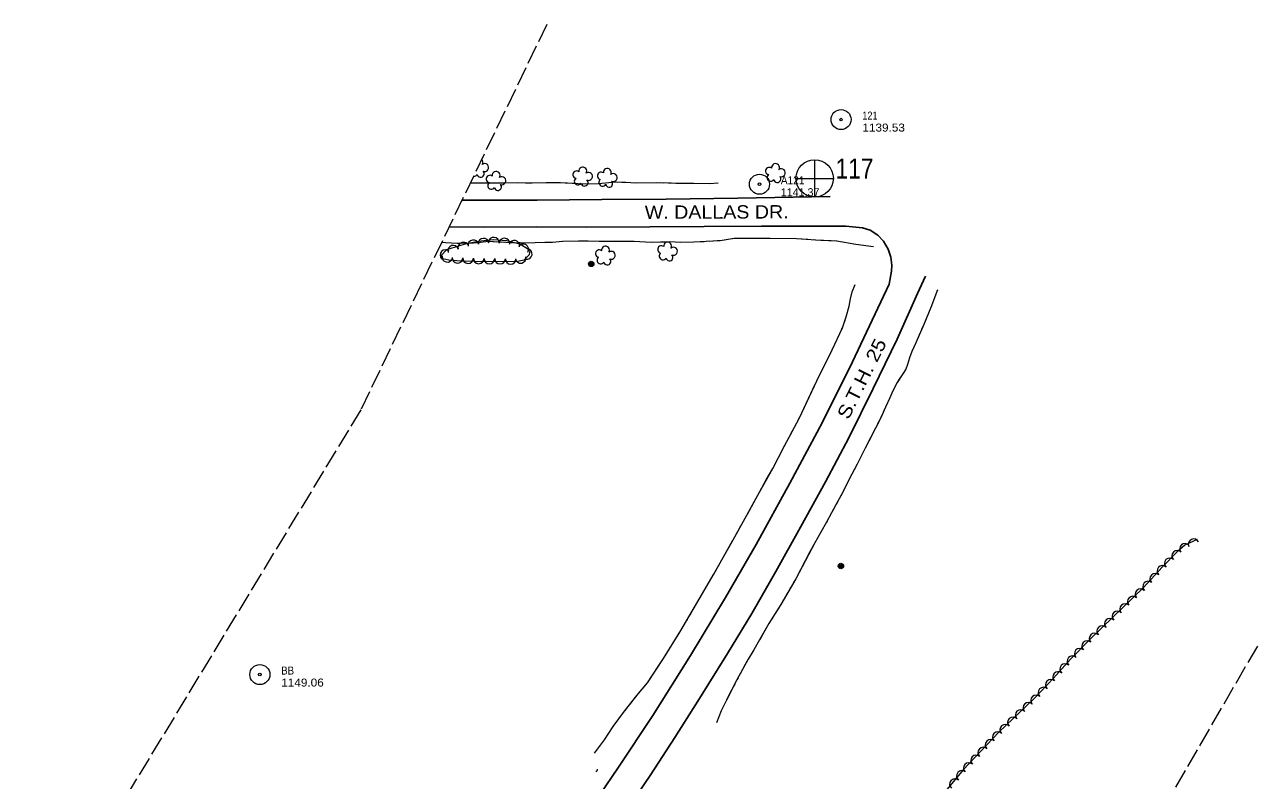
# Model space of a CAD drawing. Extents: x 301157 to 303663, y 52185 to 54539.
# Drawn here: x 302144 to 303068, y 53343 to 53910 of the extents above; entities that cross this region are included whole.
import ezdxf

# ---------------------------------------------------------------- set-up
doc = ezdxf.new("R2010")
doc.units = 0
doc.header["$LTSCALE"] = 2.4
doc.linetypes.add('LONG_DASHED', pattern=[7.5, 6, -1.5])
for name, color, linetype, lineweight in [('11', 7, 'Continuous', 25), ('14', 7, 'Continuous', 13), ('15', 7, 'Continuous', 13), ('18', 7, 'Continuous', 13), ('19', 7, 'Continuous', 13), ('4', 7, 'Continuous', 13), ('6', 7, 'Continuous', 13)]:
    doc.layers.add(name, color=color, linetype=linetype, lineweight=lineweight)

msp = doc.modelspace()

# ---------------------------------------------------------------- linework, layer by layer
at = {"layer": '11'}
for points in [[(302748.12, 53780.74), (302720.461, 53780.312), (302678.818, 53779.643), (302625.184, 53778.826), (302576.883, 53778.434), (302528.48, 53777.953), (302483.979, 53778.022), (302471.984, 53777.974)], [(302462.37, 53758.053), (302488.449, 53757.824), (302528.071, 53758.107), (302565.172, 53757.901), (302612.95, 53758.038), (302653.56, 53758.281), (302696.71, 53758.662), (302731.534, 53758.637), (302759.808, 53758.471), (302772.335, 53757.239), (302778.061, 53755.629), (302783.915, 53751.863), (302788.127, 53747.346), (302791.568, 53741.213), (302793.501, 53735.397), (302794.461, 53729.339), (302794.085, 53724.792), (302792.333, 53715.001), (302764.742, 53656.644), (302742.002, 53610.915), (302717.971, 53565.75), (302692.746, 53519.734), (302669.6, 53479.916), (302643.445, 53436.361), (302615.208, 53391.529), (302588.941, 53351.821), (302562.487, 53312.98)], [(302590.369, 53312.818), (302613.105, 53346.396), (302631.621, 53374.962), (302650.2, 53404.186), (302671.229, 53437.906), (302689.338, 53468.019), (302707.415, 53499.563), (302725.953, 53532.685), (302744.702, 53566.827), (302762.011, 53599.746), (302780.469, 53636.767), (302798.263, 53673.828), (302813.716, 53708.052), (302819.521, 53721.117)]]:
    msp.add_lwpolyline(points, dxfattribs=at)
at = {"layer": '14'}
for centre, radius in [((302568.933, 53730.187), 2.018), ((302568.922, 53730.194), 1.518), ((302568.956, 53730.173), 1.008), ((302568.951, 53730.182), 0.502), ((302756.146, 53503.564), 2.018), ((302756.135, 53503.571), 1.518), ((302756.169, 53503.55), 1.008), ((302756.164, 53503.559), 0.502)]:
    msp.add_circle(centre, radius, dxfattribs=at)
at = {"layer": '15'}
msp.add_arc((302572.452, 53350.88), 1.257, 271.47424, 17.7138, dxfattribs=at)
at = {"layer": '18'}
msp.add_lwpolyline([(302512.501, 53731.917), (302518.545, 53733.193), (302522.664, 53737.242), (302523.217, 53740.32), (302515.447, 53745.103), (302505.579, 53747.471), (302495.43, 53748.292), (302484.234, 53747.099), (302473.358, 53744.869), (302460.406, 53740.717), (302456.517, 53736.587), (302457.633, 53734.167), (302462.215, 53733.194), (302471.134, 53732.617), (302481.868, 53732.331)], close=True, dxfattribs=at)
msp.add_lwpolyline([(303023.41, 53523.48), (303014.024, 53519.115), (303008.086, 53513.917), (302997.199, 53502.874), (302982.89, 53487.313), (302960.068, 53465.27), (302943.057, 53448.804), (302928.36, 53433.726), (302915.552, 53419.544), (302901.279, 53404.516), (302874.497, 53378.955), (302847.963, 53350.654), (302828.253, 53327.174)], dxfattribs=at)
for centre, radius, start, end in [((302484.701, 53806.423), 2.974, 327.63186, 46.39781), ((302481.127, 53798.884), 2.783, 262.10554, 328.29081), ((302486.066, 53797.874), 2.611, 189.98791, 47.92051), ((302489.06, 53802.515), 2.975, 245.28267, 128.25594), ((302497.643, 53796.537), 2.974, 327.63186, 188.86574), ((302557.927, 53797.196), 2.777, 50.60275, 258.37574), ((302562.627, 53799.8), 2.974, 327.63186, 188.86574), ((302566.986, 53795.892), 2.975, 245.28267, 128.25594), ((302576.316, 53796.346), 2.777, 50.60275, 258.37574), ((302581.016, 53798.95), 2.974, 327.63186, 188.86574), ((302585.375, 53795.042), 2.975, 245.28267, 128.25594), ((302702.477, 53799.916), 2.777, 50.60275, 258.37574), ((302707.177, 53802.52), 2.974, 327.63186, 188.86574), ((302711.536, 53798.612), 2.975, 245.28267, 128.25594), ((302492.943, 53793.933), 2.777, 50.60275, 258.37574), ((302494.069, 53788.998), 2.783, 127.27976, 328.29081), ((302499.008, 53787.988), 2.611, 189.98791, 47.92051), ((302502.002, 53792.629), 2.975, 245.28267, 128.25594), ((302559.053, 53792.261), 2.783, 127.27976, 328.29081), ((302563.992, 53791.251), 2.611, 189.98791, 47.92051), ((302577.442, 53791.411), 2.783, 127.27976, 328.29081), ((302582.381, 53790.401), 2.611, 189.98791, 47.92051), ((302703.603, 53794.981), 2.783, 127.27976, 328.29081), ((302708.542, 53793.971), 2.611, 189.98791, 47.92051), ((302465.412, 53740.126), 3.996, 17.78186, 197.76654), ((302473.021, 53742.565), 3.996, 17.78186, 197.76654), ((302480.603, 53744.22), 3.996, 11.59491, 191.57959), ((302488.289, 53745.428), 3.996, 6.08992, 186.07459), ((302495.845, 53746.16), 3.996, 355.38281, 175.36749), ((302503.81, 53745.516), 3.996, 355.38281, 175.36749), ((302511.3, 53743.947), 3.996, 346.51369, 166.49836), ((302517.951, 53741.106), 3.996, 328.39234, 148.37702), ((302579.665, 53740.581), 2.974, 327.63186, 188.86574), ((302621.549, 53741.044), 2.777, 50.60275, 258.37574), ((302626.249, 53743.648), 2.974, 327.63186, 188.86574), ((302630.608, 53739.74), 2.975, 245.28267, 128.25594), ((302459.595, 53736.805), 3.996, 46.72909, 226.71377), ((302461.058, 53735.578), 3.996, 168.01884, 348.00352), ((302468.7, 53734.87), 3.996, 176.30616, 356.29084), ((302476.604, 53734.563), 3.996, 178.48142, 358.46609), ((302484.565, 53734.386), 3.996, 179.23337, 359.21804), ((302492.555, 53734.278), 3.996, 179.23337, 359.21804), ((302500.545, 53734.17), 3.996, 179.23337, 359.21804), ((302508.535, 53734.062), 3.996, 179.23337, 359.21804), ((302515.979, 53734.789), 3.996, 191.9288, 11.91348), ((302520.612, 53737.645), 3.996, 259.82244, 79.80712), ((302574.965, 53737.977), 2.777, 50.60275, 258.37574), ((302576.091, 53733.042), 2.783, 127.27976, 328.29081), ((302581.03, 53732.032), 2.611, 189.98791, 47.92051), ((302584.024, 53736.673), 2.975, 245.28267, 128.25594), ((302622.675, 53736.109), 2.783, 127.27976, 328.29081), ((302627.614, 53735.099), 2.611, 189.98791, 47.92051), ((303014.185, 53516.481), 3.989, 41.20588, 221.19056), ((303020.674, 53519.905), 3.989, 24.94865, 204.93333), ((303008.38, 53511.242), 3.989, 45.41523, 225.39991), ((302997.284, 53499.883), 3.989, 47.40781, 227.39249), ((303002.78, 53505.562), 3.989, 45.41523, 225.39991), ((302991.885, 53494.011), 3.989, 47.40781, 227.39249), ((302980.792, 53482.384), 3.989, 44.01292, 223.9976), ((302986.486, 53488.14), 3.989, 47.40781, 227.39249), ((302969.317, 53471.301), 3.989, 44.01292, 223.9976), ((302975.054, 53476.842), 3.989, 44.01292, 223.9976), ((302963.58, 53465.76), 3.989, 44.01292, 223.9976), ((302952.117, 53454.668), 3.989, 44.07498, 224.05966), ((302957.848, 53460.216), 3.989, 44.07498, 224.05966), ((302940.807, 53443.505), 3.989, 45.74078, 225.72546), ((302946.386, 53449.121), 3.989, 44.07498, 224.05966), ((302935.24, 53437.793), 3.989, 45.74078, 225.72546), ((302924.388, 53426.213), 3.989, 47.92194, 227.90662), ((302929.734, 53432.133), 3.989, 47.92194, 227.90662), ((302913.566, 53414.422), 3.989, 46.48368, 226.46836), ((302919.042, 53420.293), 3.989, 47.92194, 227.90662), ((302908.073, 53408.638), 3.989, 46.48368, 226.46836), ((302896.727, 53397.286), 3.989, 43.67137, 223.65605), ((302902.497, 53402.793), 3.989, 43.67137, 223.65605), ((302890.957, 53391.779), 3.989, 43.67137, 223.65605), ((302879.416, 53380.764), 3.989, 43.67137, 223.65605), ((302885.187, 53386.271), 3.989, 43.67137, 223.65605), ((302868.397, 53369.397), 3.989, 46.85332, 226.838), ((302873.853, 53375.216), 3.989, 46.85332, 226.838), ((302862.942, 53363.578), 3.989, 46.85332, 226.838), ((302852.03, 53351.94), 3.989, 46.85332, 226.838), ((302857.486, 53357.759), 3.989, 46.85332, 226.838), ((302846.825, 53346.052), 3.989, 49.99629, 229.98097), ((302841.697, 53339.942), 3.989, 49.99629, 229.98097)]:
    msp.add_arc(centre, radius, start, end, dxfattribs=at)
at = {"layer": '19'}
for p, q in [((302478.303, 53791.068), (302478.926, 53791.075)), ((302482.542, 53791.063), (302484.351, 53791.039)), ((302487.967, 53790.991), (302489.775, 53790.967)), ((302549.425, 53791.078), (302551.232, 53791.019)), ((302560.256, 53790.535), (302562.059, 53790.401)), ((302621.651, 53791.216), (302623.457, 53791.155)), ((302627.071, 53791.034), (302628.878, 53790.973)), ((302503.929, 53746.313), (302501.985, 53746.416)), ((302509.762, 53746.005), (302507.818, 53746.108)), ((302515.602, 53745.924), (302513.655, 53745.946)), ((302581.738, 53747.087), (302579.791, 53747.098)), ((302587.579, 53747.052), (302585.632, 53747.063)), ((302593.419, 53747.039), (302591.473, 53747.032)), ((302659.544, 53747.211), (302657.601, 53747.105)), ((302665.374, 53747.532), (302663.431, 53747.425)), ((302671.135, 53748.485), (302669.215, 53748.16)), ((302737.209, 53748.08), (302735.268, 53748.22)), ((302743.042, 53747.781), (302741.098, 53747.88)), ((302748.876, 53747.486), (302746.931, 53747.585)), ((302754.147, 53675.456), (302755.009, 53677.283)), ((302815.221, 53677.75), (302814.483, 53676.081)), ((302817.436, 53682.758), (302816.698, 53681.089)), ((302751.561, 53669.977), (302752.423, 53671.803)), ((302813.006, 53672.743), (302812.268, 53671.073)), ((302786.882, 53616.683), (302786.125, 53615.021)), ((302718.785, 53602.838), (302719.719, 53604.629)), ((302721.588, 53608.21), (302722.523, 53610.001)), ((302782.006, 53606.874), (302781.181, 53605.245)), ((302784.482, 53611.76), (302783.657, 53610.131)), ((302715.981, 53597.465), (302716.916, 53599.256)), ((302753.687, 53551.648), (302752.81, 53550.047)), ((302683.083, 53537.172), (302684.064, 53538.938)), ((302748.366, 53542.071), (302747.491, 53540.468)), ((302751.029, 53546.859), (302750.136, 53545.266)), ((302680.141, 53531.874), (302681.122, 53533.64)), ((302660.915, 53497.488), (302675.237, 53523.044)), ((302677.199, 53526.575), (302678.18, 53528.341)), ((302718.6, 53487.599), (302717.682, 53486.021)), ((302713.09, 53478.128), (302712.172, 53476.549)), ((302715.845, 53482.864), (302714.927, 53481.285)), ((302643.083, 53466.955), (302644.117, 53468.691)), ((302636.874, 53456.543), (302637.909, 53458.279)), ((302639.979, 53461.749), (302641.013, 53463.485)), ((302681.669, 53424.595), (302680.798, 53422.99)), ((302676.504, 53414.931), (302675.663, 53413.309)), ((302598.137, 53399.941), (302599.389, 53401.525)), ((302590.763, 53390.33), (302591.965, 53391.954)), ((302594.383, 53395.19), (302595.634, 53396.774))]:
    msp.add_line(p, q, dxfattribs=at)
for points in [[(302478.303, 53791.068), (302480.428, 53791.091), (302491.957, 53790.938), (302503.32, 53791.063), (302513.36, 53791.302), (302524.595, 53791.035), (302535.106, 53791.272), (302544.233, 53791.246), (302555.691, 53790.875), (302562.572, 53790.363), (302574.08, 53790.48), (302584.827, 53791.609), (302587.913, 53791.7), (302594.969, 53791.529), (302602.402, 53791.158), (302620.266, 53791.262), (302632.986, 53790.835), (302645.798, 53790.759), (302657.782, 53790.652), (302664.121, 53791.048)], [(302493.391, 53790.954), (302503.32, 53791.063), (302513.36, 53791.302), (302519.601, 53791.154)], [(302519.601, 53791.154), (302524.595, 53791.035), (302535.106, 53791.272), (302544.233, 53791.246), (302545.812, 53791.195)], [(302554.845, 53790.902), (302555.691, 53790.875), (302556.65, 53790.804)], [(302565.674, 53790.395), (302574.08, 53790.48), (302584.827, 53791.609), (302587.913, 53791.7), (302591.829, 53791.605)], [(302591.829, 53791.605), (302594.969, 53791.529), (302602.402, 53791.158), (302618.035, 53791.249)], [(302632.492, 53790.852), (302632.986, 53790.835), (302634.3, 53790.827)], [(302637.916, 53790.806), (302645.798, 53790.759), (302657.782, 53790.652), (302664.121, 53791.048)], [(302780.619, 53742.923), (302767.482, 53744.705), (302752.995, 53747.278), (302737.37, 53748.068), (302722.945, 53749.114), (302700.047, 53749.203), (302676.18, 53749.341), (302665.579, 53747.543), (302655.117, 53746.968), (302645.8, 53746.461), (302636.241, 53746.236), (302627.628, 53746.669), (302613.861, 53746.309), (302601.117, 53747.065), (302591.048, 53747.031), (302575.007, 53747.127), (302566.707, 53747.393), (302559.319, 53747.283), (302547.478, 53747.133), (302539.934, 53746.338), (302534.271, 53746.224), (302519.745, 53745.878), (302510.138, 53745.985), (302499.57, 53746.543), (302491.892, 53747.058), (302485.896, 53746.408), (302480.765, 53745.742), (302468.33, 53745.46), (302459.883, 53746.031), (302456.662, 53746.226)], [(302469.974, 53745.497), (302468.33, 53745.46), (302459.883, 53746.031), (302456.662, 53746.226)], [(302498.097, 53746.642), (302491.892, 53747.058), (302485.896, 53746.408), (302480.765, 53745.742), (302469.974, 53745.497)], [(302547.676, 53747.136), (302547.478, 53747.133), (302539.934, 53746.338), (302534.271, 53746.224), (302519.745, 53745.878), (302519.495, 53745.881)], [(302575.898, 53747.122), (302575.007, 53747.127), (302566.707, 53747.393), (302559.319, 53747.283), (302547.676, 53747.136)], [(302625.515, 53746.614), (302613.861, 53746.309), (302601.117, 53747.065), (302597.312, 53747.052)], [(302653.713, 53746.892), (302645.8, 53746.461), (302636.241, 53746.236), (302627.628, 53746.669), (302625.515, 53746.614)], [(302703.184, 53749.191), (302700.047, 53749.203), (302676.18, 53749.341), (302674.973, 53749.136)], [(302731.384, 53748.502), (302722.945, 53749.114), (302703.184, 53749.191)], [(302780.619, 53742.923), (302767.482, 53744.705), (302752.995, 53747.278), (302752.765, 53747.29)], [(302571.343, 53363.266), (302578.967, 53373.219), (302585.455, 53383.156), (302594.014, 53394.723), (302603.26, 53406.424), (302611.134, 53416.027), (302623.025, 53434.105), (302635.264, 53453.843), (302647.234, 53473.917), (302660.467, 53496.689), (302675.386, 53523.309), (302684.301, 53539.366), (302693.895, 53556.633), (302705.005, 53576.841), (302713.714, 53593.12), (302725.011, 53614.77), (302738.108, 53642.487), (302749.566, 53665.75), (302757.347, 53682.236), (302760.178, 53690.517), (302762.259, 53698.48), (302763.356, 53704.127), (302764.695, 53709.225), (302766.82, 53714.684)], [(302758.841, 53686.606), (302760.178, 53690.517), (302762.259, 53698.48), (302763.356, 53704.127), (302764.695, 53709.225), (302766.82, 53714.684)], [(302828.564, 53710.737), (302823.631, 53697.498), (302818.27, 53684.643), (302812.255, 53671.045), (302809.456, 53664.563), (302807.51, 53659.766), (302806.197, 53654.795), (302804.792, 53651.314), (302802.543, 53647.67), (302798.307, 53641.256), (302795.222, 53634.976), (302792.758, 53629.661), (302789.699, 53622.869), (302786.033, 53614.819), (302774.411, 53591.889), (302768.481, 53580.06), (302764.466, 53572.429), (302761.354, 53566.604), (302757.391, 53558.409), (302752.479, 53549.443), (302749.172, 53543.549), (302745.255, 53536.369), (302741.073, 53528.898), (302736.503, 53520.974), (302722.271, 53493.91), (302711.082, 53474.676), (302702.076, 53460.481), (302695.179, 53448.134), (302690.872, 53440.651), (302686.548, 53433.584), (302678.203, 53418.209), (302670.325, 53403.011), (302666.483, 53394.875), (302662.97, 53386.009)], [(302828.564, 53710.737), (302823.631, 53697.498), (302818.882, 53686.11)], [(302756.733, 53680.936), (302757.347, 53682.236), (302757.535, 53682.786)], [(302736.949, 53640.034), (302738.108, 53642.487), (302749.566, 53665.75), (302749.837, 53666.324)], [(302810.819, 53667.72), (302809.456, 53664.563), (302807.51, 53659.766), (302806.197, 53654.795), (302804.792, 53651.314), (302802.543, 53647.67), (302799.967, 53643.77)], [(302799.967, 53643.77), (302798.307, 53641.256), (302795.222, 53634.976), (302792.758, 53629.661), (302789.699, 53622.869), (302788.396, 53620.008)], [(302724.392, 53613.583), (302725.011, 53614.77), (302736.949, 53640.034)], [(302779.53, 53601.988), (302774.411, 53591.889), (302768.481, 53580.06), (302767.587, 53578.362)], [(302700.202, 53568.104), (302705.005, 53576.841), (302713.714, 53593.12), (302714.112, 53593.883)], [(302767.587, 53578.362), (302764.466, 53572.429), (302761.354, 53566.604), (302757.391, 53558.409), (302755.441, 53554.85)], [(302686.026, 53542.47), (302693.895, 53556.633), (302700.202, 53568.104)], [(302745.742, 53537.261), (302745.255, 53536.369), (302741.073, 53528.898), (302736.503, 53520.974), (302732.898, 53514.119)], [(302732.898, 53514.119), (302722.271, 53493.91), (302720.437, 53490.757)], [(302646.187, 53472.161), (302647.234, 53473.917), (302660.467, 53496.689), (302660.915, 53497.488)], [(302710.286, 53473.422), (302702.076, 53460.481), (302696.636, 53450.742)], [(302619.196, 53428.284), (302623.025, 53434.105), (302634.791, 53453.081)], [(302696.636, 53450.742), (302695.179, 53448.134), (302690.872, 53440.651), (302686.548, 53433.584), (302683.412, 53427.806)], [(302601.892, 53404.693), (302603.26, 53406.424), (302611.134, 53416.027), (302619.196, 53428.284)], [(302679.055, 53419.779), (302678.203, 53418.209), (302678.185, 53418.174)], [(302673.982, 53410.066), (302670.325, 53403.011), (302666.483, 53394.875), (302662.97, 53386.009)], [(302571.343, 53363.266), (302578.967, 53373.219), (302585.455, 53383.156), (302588.36, 53387.081)]]:
    msp.add_lwpolyline(points, dxfattribs=at)
at = {"layer": '4'}
for p, q in [((302736.443, 53808.388), (302736.378, 53780.534)), ((302722.534, 53794.358), (302750.439, 53794.345))]:
    msp.add_line(p, q, dxfattribs=at)
at = {"layer": '4', "linetype": 'LONG_DASHED'}
for points in [[(302535.574, 53909.742), (302396.163, 53620.863), (302177.225, 53260.058), (301955.887, 52952.13)], [(303068.442, 53443.529), (302957.716, 53252.268), (302726.776, 52938.162), (302416.216, 52571.488)]]:
    msp.add_lwpolyline(points, dxfattribs=at)
at = {"layer": '4'}
msp.add_circle((302736.495, 53794.366), 14, dxfattribs=at)
at = {"layer": '6'}
for centre, radius in [((302756.271, 53838.513), 7.5), ((302756.271, 53838.513), 0.96), ((302695.097, 53790.014), 7.5), ((302695.097, 53790.014), 0.96), ((302320.477, 53422.136), 7.5), ((302320.477, 53422.136), 0.96)]:
    msp.add_circle(centre, radius, dxfattribs=at)

# ---------------------------------------------------------------- texts
at = {"layer": '11'}
for s, rotation, width, p in [('W. DALLAS DR.', 0.164, 1.1, (302609.087, 53764.027)), ('S.T.H. 25', 63.5, 1.15, (302761.819, 53612.808))]:
    msp.add_text(s, height=10, rotation=rotation, dxfattribs=dict(at, width=width)).set_placement(p)
at = {"layer": '4', "width": 0.85}
msp.add_text('117', height=15, dxfattribs=at).set_placement((302752.147, 53794.296))
at = {"layer": '6'}
for s, width, p in [('121', 0.85, (302772.271, 53838.513)), ('1139.53', 1.1, (302772.271, 53829.513)), ('A121', 0.95, (302711.097, 53790.014)), ('BB', 0.9, (302336.477, 53422.136)), ('1149.06', 1.1, (302336.477, 53413.136))]:
    msp.add_text(s, height=6, dxfattribs=dict(at, width=width)).set_placement(p)
msp.add_text('1141.37', height=6, dxfattribs=at).set_placement((302711.097, 53781.014))

doc.saveas('drawing.dxf')
